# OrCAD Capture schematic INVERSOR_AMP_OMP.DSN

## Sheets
1 inversor: size A
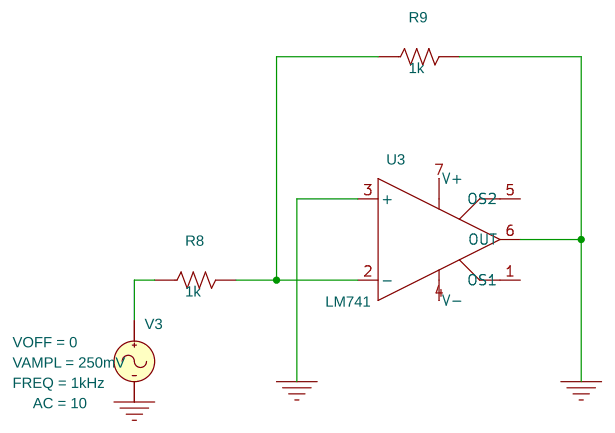
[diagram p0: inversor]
2 no inversosr: size A
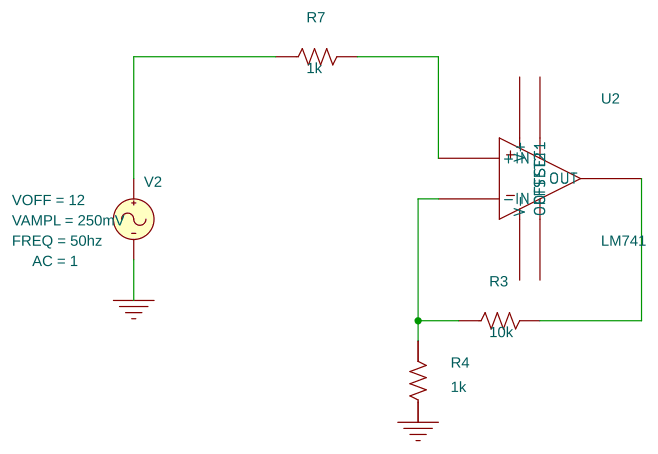
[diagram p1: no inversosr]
3 PAGE1: size A
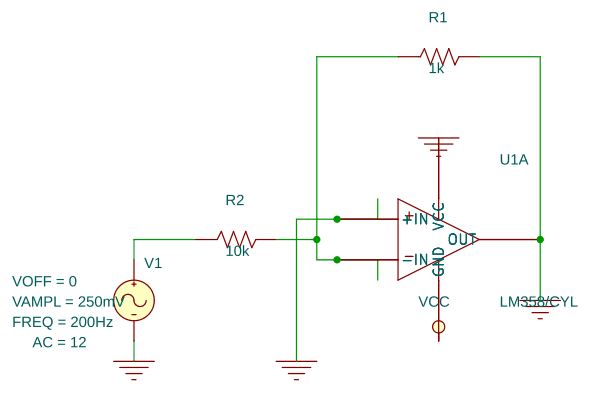
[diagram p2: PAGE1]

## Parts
sheet inversor
R8  1k  [AX/RC05]
R9  1k  [AX/RC05]
U3  LM741  [DIP1008W300L450]
V3  VSIN
sheet no inversosr
R3  10k  [AX/RC05]
R4  1k  [AX/RC05]
R7  1k  [AX/RC05]
U2  LM741
V2  VSIN
sheet PAGE1
R1  1k  [AX/RC05]
R2  10k  [AX/RC05]
U1  LM358/CYL  (section A)
V1  VSIN

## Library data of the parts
R8 R9 = r
U3 = LM741
V3 = VSIN: AC: 10; FREQ: 1kHz; VAMPL: 250mV; VOFF: 0
R1-R4 R7 = R
U2 = LM741_v2
V2 = VSIN: AC: 1; FREQ: 50hz; VAMPL: 250mV; VOFF: 12
U1 = LM358_CYL
V1 = VSIN: AC: 12; FREQ: 200Hz; VAMPL: 250mV; VOFF: 0

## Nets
GND: R9.2 U3.3(+) U3.6(OUT) V3.2(-)
VCC: U1.4(GND)
0: R1.2 R4.1 U1.1(OUT) U1.3(+IN) U1.8(VCC) V1.2(-) V2.2(-)
V+: U2.7(V+) U3.7(V+)
V-: U2.4(V-) U3.4(V-)
N02538: R2.1 V1.1(+)
N04314: R1.1 R2.2 U1.2(-IN)
N05132: R7.1 V2.1(+)
N05139: R3.1 R4.2 U2.2(-IN)
N05561: R7.2 U2.3(+IN)
N06123: R3.2 U2.6(OUT)
N06795: R8.1 V3.1(+)
N06802: R8.2 R9.1 U3.2(-)

Not connected (* = marked no-connect by the designer): U2 1(OFFSET1) 5(OFFSET2); U3 1(OS1) 5(OS2)
